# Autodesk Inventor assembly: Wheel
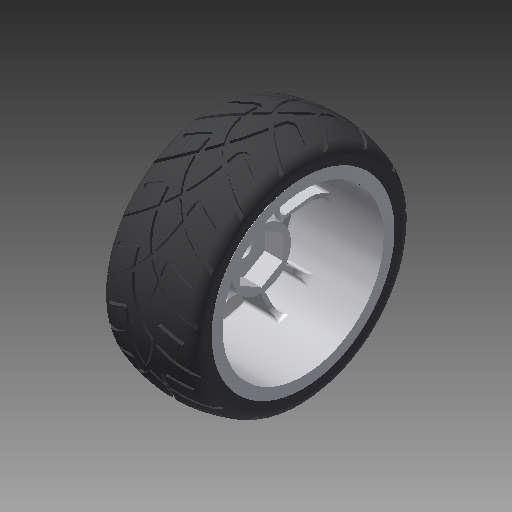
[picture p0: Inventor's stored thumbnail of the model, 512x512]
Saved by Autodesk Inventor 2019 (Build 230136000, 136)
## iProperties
Shininess: 50.0
Compacted: True
Length Units: 11272
Angle Units: 11279
Time Units: 11290
Mass Units: 11286
Length Display Precision: 4
Angle Display Precision: 2
Company: Autodesk
Created: 2000-05
Part Number: Wheel
Project: Inventor Samples
User Status: IN PROGRESS
Description: ASSEMBLY - WHEEL (LEFT)
Document SubType Name: Assembly
Designer: The PD Team
Mass: 35.0352 g
Surface Area: 335.101 cm^2
Volume: 19.2965 cm^3
Density: 1.81563 g/cm^3
Density: 0.0
Volumn: 0.0
Area: 0.0
PropertySet Name: Model Information
Control State: 0
Master: False
Checked Out: False
Checked Out Date: 2018-05-30
Last Check In Date: 2018-05-30
Author: The PD Team
Revision Number: A
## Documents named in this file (3)
- C:\Users\itools\Desktop\autodesk_inventor_2018_samples\Models\Assemblies\Suspension\Components\Wheel R.iam
- C:\Users\itools\Desktop\autodesk_inventor_2018_samples\Models\Assemblies\Suspension\Components\Wheel.ipt
- C:\Users\itools\Desktop\autodesk_inventor_2018_samples\Models\Assemblies\Suspension\Components\Tire - 2.ipt
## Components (2 placed, 2 different names)
1. Wheel:1 — Insert:1
2. Tire - 2:1 — Insert:1
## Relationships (1: Insert 1)
- Insert:1: Wheel:1 ↔ Tire - 2:1
